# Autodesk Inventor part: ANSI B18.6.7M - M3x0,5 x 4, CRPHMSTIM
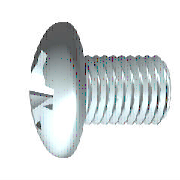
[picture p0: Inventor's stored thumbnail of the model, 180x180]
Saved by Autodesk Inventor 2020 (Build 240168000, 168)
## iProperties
Created: 2019-01
Part Number: ANSI B18.6.7M - M3x0,5 x 4, CRPHMSTIM
Material: Acier, doux
Description: Vis à tête tronconique à empreinte cruciforme - Type IA - Métrique
Document SubType Name: Modeling
Standard: ANSI B18.6.7M
Designer: bruno
Standard Revision: 2005
Standards Organization: ANSI
Language: fr-FR
Size Designation: M3x0,5 x 4
Categories: <MemberInstance><Categories><Category DisplayName="Visserie" InternalName="e4da775c-781d-43d5-af7c-5136215cf5a6" Mnemonic="FSTN"><Category DisplayName="Vis" Int
Density: 7.85 g/cm^3
Appearance: Semi-poli
IsCustomPart: 0
Author: bruno
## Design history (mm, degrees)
workplane "Work Plane3"
sketch "Esquisse4"
  geometry: L1 (-9, 0)-(9, 0) reference; L2 (0, -9)-(0, 9) reference; L3 (0, 0)-(6.428, 6.428); L4 (0, 0)-(6.428, -6.428); L5 (0, 0)-(-6.428, 6.428); L6 (0, 0)-(-6.428, -6.428); L7 (1.011, 1.011)-(0, 0.183); L8 (-1.011, 1.011)-(-0.182, 0); L9 (-1.011, -1.011)-(0, -0.183); L10 (1.011, -1.011)-(0.182, 0); L11 (1.011, 1.011)-(0.182, 0); L12 (-1.011, 1.011)-(0, 0.183); L13 (-1.011, -1.011)-(-0.182, 0); L14 (1.011, -1.011)-(0, -0.183); C1 r 2.8 at (0, 0) reference; A1 r 0.182 centre (0, 0) between (0, 0.183) and (-0.182, 0); A2 r 1.43 centre (0, 0) between (1.011, 1.011) and (1.011, -1.011); 1 further point
  constraints: 24 end point, 10 point on line, 7 point on circle, 3 perpendicular, 3 symmetric about line, 2 centre point, 2 coincident, 3 other
  dimensions: "d11" = 0.365 diameter of A1 (= 0.5 x SBR); "d14" = 45 deg angle of L3 L1; "d35" = 1.01116 distance from line of L1 L7.start (= 0.353553 x SDM)
extrude "Coupe en étoile" cut sketch "Esquisse4" distance "d12" = 2.4 (= KOH); taper "d13" = -10 deg
sketch "Esquisse2"
  geometry: L1 (-4.704, 0)-(8.625, 0) reference; L2 (0, -4.704)-(0, 8.625) reference; L3 (0, 1.43)-(0, 0); L4 (0, 0)-(1.43, 0); L5 (0, 0)-(6.721, 6.721); L6 (0.365, 1.383)-(0.213, 0.683); L7 (1.383, 0.365)-(0.683, 0.213); L8 (1.383, -0.365)-(0.683, -0.213); L9 (0.365, -1.383)-(0.213, -0.683); L10 (-0.365, 1.383)-(-0.213, 0.683); L11 (-1.383, 0.365)-(-0.683, 0.213); L12 (-0.365, -1.383)-(-0.213, -0.683); L13 (-1.383, -0.365)-(-0.683, -0.213); C1 r 2.8 at (0, 0) reference; A1 r 0.572 centre (0, 0) between (0.572, 0) and (0, 0.572); A2 r 0.181 centre (0.389, 0.644) between (0.213, 0.683) and (0.517, 0.517); A3 r 0.181 centre (0.644, 0.389) between (0.517, 0.517) and (0.683, 0.213); A4 r 1.43 centre (0, 0) between (1.43, 0) and (1.383, 0.365); A5 r 1.43 centre (0, 0) between (0.365, 1.383) and (0, 1.43); A6 r 1.43 centre (0, 0) between (1.383, 0.365) and (0.365, 1.383); A7 r 1.43 centre (0, 0) between (0, -1.43) and (0.365, -1.383); A8 r 1.43 centre (0, 0) between (0.365, -1.383) and (1.383, -0.365); A9 r 1.43 centre (0, 0) between (1.383, -0.365) and (1.43, 0); A10 r 0.181 centre (0.389, -0.644) between (0.517, -0.517) and (0.213, -0.683); A11 r 0.181 centre (0.644, -0.389) between (0.683, -0.213) and (0.517, -0.517); A12 r 0.181 centre (-0.389, 0.644) between (-0.517, 0.517) and (-0.213, 0.683); A13 r 0.181 centre (-0.644, 0.389) between (-0.683, 0.213) and (-0.517, 0.517); A14 r 1.43 centre (0, 0) between (-1.383, 0.365) and (-1.43, 0); A15 r 1.43 centre (0, 0) between (-0.365, 1.383) and (-1.383, 0.365); A16 r 1.43 centre (0, 0) between (0, 1.43) and (-0.365, 1.383); A17 r 1.43 centre (0, 0) between (-1.43, 0) and (-1.383, -0.365); A18 r 1.43 centre (0, 0) between (-1.383, -0.365) and (-0.365, -1.383); A19 r 1.43 centre (0, 0) between (-0.365, -1.383) and (0, -1.43); A20 r 0.181 centre (-0.644, -0.389) between (-0.517, -0.517) and (-0.683, -0.213); A21 r 0.181 centre (-0.389, -0.644) between (-0.213, -0.683) and (-0.517, -0.517); A22 r 0.715 centre (0, 0) between (0.715, 0) and (0, 0.715)
  constraints: 46 point on circle, 25 symmetric about line, 22 centre point, 22 end point, 6 tangent, 4 coincident, 3 collinear, 3 point on line, 1 midpoint, 1 perpendicular, 22 other
  dimensions: "d4" = 45 deg angle of L5 L4; "d5" = 1.144 diameter of A1 (= 0.4 x SDM); "d6" = 2.86 diameter of A6 (= SDM); "d7" = 0.365 distance from line of L6.start L3 (= 0.5 x SBR); "d20" = 1.43 diameter of A22 (= 0.5 x SDM)
extrude "Rainure" join sketch "Esquisse2" taper "d21" = 5 deg; stored distance "d54" = 10
revolve "Coupe" stored, may be unused: angle "d56" = 90 deg
revolve "Corps" stored, may be unused: angle "d18" = 90 deg
node "IDS_WORKPLANE{1}"
body "Solid1"
sketch "Esquisse1"
  geometry: L1 (4, 0)-(4, 1.5); L2 (4, 1.5)-(0.5, 1.5); L3 (3.962, 5.08)-(3.962, 5.08); L4 (-2.4, 0)-(-2.4, 2.8); L5 (-2.217, 1.339)-(-0.672, 0.569); L6 (-0.672, 0.569)-(-0.37, 0); L7 (-0.37, 0)-(4, 0); L8 (-3.931, 0)-(5.322, 0) reference; L9 (0, -1.016)-(0, 6.096) reference; L10 (-2.217, 1.339)-(-2.4, 1.43); L11 (-1.542, 2.8)-(-2.4, 2.8); L12 (-1.542, 2.8)-(0, 2.8); L13 (0, 2.8)-(0, 1.5); L14 (0, 1.5)-(0.193, 1.5); L15 (0.193, 1.5)-(0.5, 1.5); L16 (0.5, 1.5)-(0, 1.5); A1 r 5 centre (2.6, 0) between (-1.542, 2.8) and (-2.4, 0)
  constraints: 28 end point, 5 collinear, 5 point on line, 4 point on circle, 2 parallel, 2 perpendicular, 1 centre point, 1 horizontal, 1 tangent
  dimensions: "d1" = 3 diameter of L2 L7 (= GD); "d2" = 2.03 distance from line of L6.end L4 (= STI); "d16" = 2.86 diameter of L10.end L7 (= SDM); "d17" = 62 deg angle of L6 L7; "d19" = 26.5 deg angle of L5 L7; "d23" = 5.6 diameter of L12.end L7 (= KOD); "d24" = 0 deg angle of L12 L7 (computed from KEWI); "d25" = 2.4 distance between parallel lines of L4 L13 (= KOH); "d26" = 5 radius of A1 (= KR); "d28" = 3 diameter of L14 L7 (= BDM); "d29" = 3.5 distance of L1.end L2.end (= GEL); "d30" = 0.30673 distance of L14.end L2.end (= GAL); "d31" = 4 distance between parallel lines of L13 L1 (= NLG)
fillet "Congé1" dims "d32" = 1 (= RR)
fillet "Congé2" dims "d22" = 0.146 (= 0.2 x SBR)
feature "Filetage" dims "d8" = 3.5 (= GEL), "d9" = 0
chamfer "Chanfrein1" distance "d36" = 0.44 (= -0.5 x SPD + 0.5 x GD); stored, may be unused: second distance "d37" = 0.30683 (computed from GUL), angle "d81" = 45 deg
fillet "Congé3" dims "d84" = 0.1 (= R)
other parameters: "GD" = 3 (= NND) [user parameter; used in 2 equation terms], "NLG" = 4 [user parameter; used in 1 equation term], "GEL" = 3.5 [user parameter; used in 2 equation terms], "KOD" = 5.6 [user parameter; used in 1 equation term], "KOH" = 2.4 [user parameter; used in 3 equation terms], "SDM" = 2.86 [user parameter; used in 5 equation terms], "STI" = 2.03 [user parameter; used in 1 equation term], "SBR" = 0.73 [user parameter; used in 3 equation terms], "KEWI" = 0 [user parameter; used in 1 equation term], "d3" = -2.4 (= -KOH), "d10" = 0, "KR" = 5 [user parameter; used in 1 equation term], "BDM" = 3 (= NND) [user parameter; used in 1 equation term], "GAL" = 0.30673 (= 0.61345 x PTC) [user parameter; used in 1 equation term], "GUL" = 0.30673 (= 0.61345 x PTC) [user parameter; used in 1 equation term], "RR" = 1 [user parameter; used in 1 equation term], "SPD" = 2.12 [user parameter; used in 1 equation term], "d82" = 0, "d83" = 0, "R" = 0.1 [user parameter; used in 1 equation term], "PTC" = 0.5 [user parameter; used in 4 equation terms], "THREADDIA" = 3 [user parameter; used in 1 equation term], "TOA" = 30 deg [user parameter], "NND" = 3 [user parameter; used in 2 equation terms], "GD1" = 2.38655 (= THREADDIA - 1.2269 x PTC) [user parameter]
